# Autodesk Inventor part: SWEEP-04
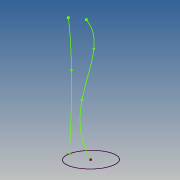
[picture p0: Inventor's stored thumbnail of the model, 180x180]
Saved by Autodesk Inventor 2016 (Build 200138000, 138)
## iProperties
Created: 2012-02
Part Number: SWEEP-04
Material: Generic
Document SubType Name: Modeling
Designer: julian.chica
Mass: 4.78738 g
Surface Area: 20.0994 cm^2
Volume: 4.78738 cm^3
Density: 1 g/cm^3
Appearance: Default
Author: julian.chica
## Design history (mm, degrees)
node "XZ- Plane Front"
sketch "PERFIL 1"
  geometry: 4 further points
  constraints: 4 other
sketch "PERFIL 2"
  geometry: 4 further points
  constraints: 3 other
sketch "PERFIL CERRADO"
  geometry: 3 further points
  constraints: 1 coincident, 1 horizontal alignment, 2 other
body "Solid2"
other parameters: "d0" = 0
